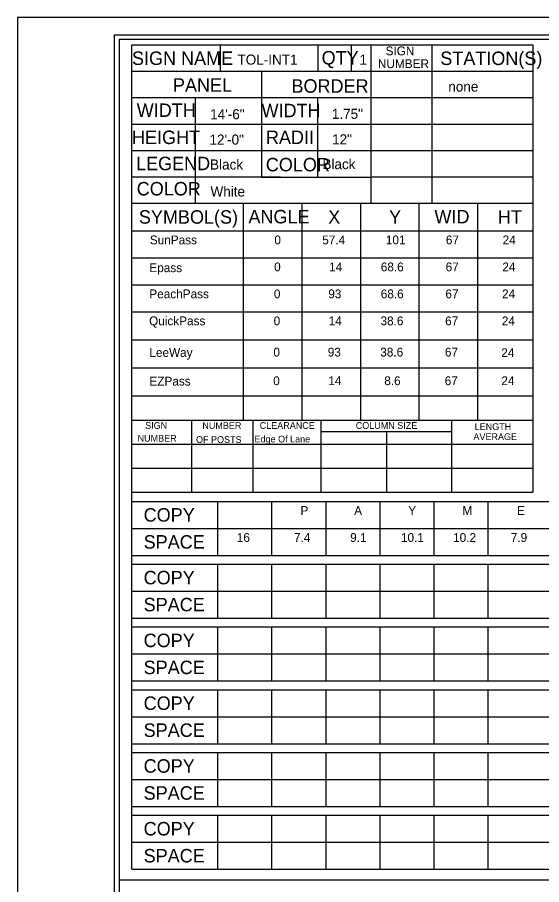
# Model space of a CAD drawing. Extents: x 17890628 to 17891459, y 17897314 to 17897992.
# Drawn here: x 17890701.35 to 17890724.69, y 17897458.18 to 17897496.82 of the extents above; entities that cross this region are included whole.
import ezdxf

# ---------------------------------------------------------------- set-up
doc = ezdxf.new("R2010")
doc.units = 0
for name, color, linetype in [('GSDims', 7, 'Continuous'), ('PlotBorder_dp', 7, 'Continuous'), ('SheetBorder_dp', 7, 'Continuous'), ('SheetLinesMisc2_dp', 7, 'Continuous'), ('TextMinor', 7, 'Continuous')]:
    doc.layers.add(name, color=color, linetype=linetype)

msp = doc.modelspace()

# ---------------------------------------------------------------- linework, layer by layer
at = {"layer": 'PlotBorder_dp'}
msp.add_lwpolyline([(17890701.346, 17897413.687), (17890830.745, 17897413.687), (17890830.745, 17897496.818), (17890701.346, 17897496.818)], close=True, dxfattribs=at)
at = {"layer": 'SheetBorder_dp'}
for q in [(17890705.659, 17897414.472), (17890826.432, 17897496.034)]:
    msp.add_line((17890705.659, 17897496.034), q, dxfattribs=at)
at = {"layer": 'SheetLinesMisc2_dp'}
for p, q in [((17890705.872, 17897495.849), (17890826.223, 17897495.849)), ((17890705.872, 17897495.849), (17890705.872, 17897420.931)), ((17890706.45, 17897458.862), (17890706.45, 17897495.599)), ((17890706.45, 17897495.599), (17890724.295, 17897495.599)), ((17890710.383, 17897495.599), (17890710.383, 17897494.422)), ((17890714.721, 17897495.599), (17890714.721, 17897494.422)), ((17890716.203, 17897495.599), (17890716.203, 17897494.422)), ((17890717.086, 17897495.599), (17890717.086, 17897488.533)), ((17890719.801, 17897495.599), (17890719.801, 17897488.533)), ((17890724.295, 17897495.599), (17890724.295, 17897475.661)), ((17890706.45, 17897494.422), (17890724.295, 17897494.422)), ((17890712.217, 17897494.422), (17890712.217, 17897489.698)), ((17890706.45, 17897493.244), (17890724.295, 17897493.244)), ((17890709.27, 17897493.244), (17890709.27, 17897488.533)), ((17890714.706, 17897493.231), (17890714.706, 17897489.698)), ((17890706.45, 17897492.066), (17890724.295, 17897492.066)), ((17890706.45, 17897490.888), (17890724.295, 17897490.888)), ((17890706.45, 17897489.711), (17890713.068, 17897489.711)), ((17890712.217, 17897489.698), (17890717.086, 17897489.698)), ((17890717.086, 17897489.711), (17890724.295, 17897489.711)), ((17890706.45, 17897488.533), (17890724.295, 17897488.533)), ((17890711.405, 17897488.51), (17890711.405, 17897478.866)), ((17890714.013, 17897488.51), (17890714.013, 17897478.866)), ((17890716.62, 17897488.51), (17890716.62, 17897478.866)), ((17890719.228, 17897488.51), (17890719.228, 17897478.866)), ((17890721.835, 17897488.51), (17890721.835, 17897478.866)), ((17890706.454, 17897487.307), (17890724.295, 17897487.307)), ((17890706.454, 17897486.105), (17890724.295, 17897486.105)), ((17890706.454, 17897484.902), (17890724.295, 17897484.902)), ((17890706.454, 17897483.7), (17890724.295, 17897483.7)), ((17890706.454, 17897482.45), (17890724.295, 17897482.45)), ((17890706.454, 17897481.2), (17890724.295, 17897481.2)), ((17890706.454, 17897479.95), (17890724.295, 17897479.95)), ((17890706.45, 17897478.866), (17890724.295, 17897478.866)), ((17890706.45, 17897478.866), (17890724.295, 17897478.866)), ((17890709.098, 17897478.866), (17890709.098, 17897475.661)), ((17890711.835, 17897478.866), (17890711.835, 17897475.661)), ((17890714.857, 17897478.866), (17890714.857, 17897475.661)), ((17890720.676, 17897478.866), (17890720.676, 17897475.661)), ((17890714.871, 17897478.362), (17890720.687, 17897478.362)), ((17890717.778, 17897478.362), (17890717.778, 17897475.661)), ((17890706.45, 17897477.798), (17890724.295, 17897477.798)), ((17890706.45, 17897476.729), (17890724.295, 17897476.729)), ((17890706.45, 17897475.661), (17890724.295, 17897475.661)), ((17890706.449, 17897475.25), (17890765.638, 17897475.25)), ((17890710.259, 17897475.25), (17890710.259, 17897472.846)), ((17890712.668, 17897475.25), (17890712.668, 17897472.846)), ((17890715.075, 17897475.25), (17890715.075, 17897472.846)), ((17890717.483, 17897475.25), (17890717.483, 17897472.846)), ((17890719.89, 17897475.25), (17890719.89, 17897472.846)), ((17890722.298, 17897475.25), (17890722.298, 17897472.846)), ((17890706.449, 17897474.048), (17890765.638, 17897474.048)), ((17890706.449, 17897472.846), (17890765.638, 17897472.846)), ((17890706.449, 17897472.453), (17890765.638, 17897472.453)), ((17890710.259, 17897472.453), (17890710.259, 17897470.049)), ((17890712.668, 17897472.453), (17890712.668, 17897470.049)), ((17890715.075, 17897472.453), (17890715.075, 17897470.049)), ((17890717.483, 17897472.453), (17890717.483, 17897470.049)), ((17890719.89, 17897472.453), (17890719.89, 17897470.049)), ((17890722.298, 17897472.453), (17890722.298, 17897470.049)), ((17890706.449, 17897471.251), (17890765.638, 17897471.251)), ((17890706.449, 17897470.049), (17890765.638, 17897470.049)), ((17890706.449, 17897469.657), (17890765.638, 17897469.657)), ((17890710.259, 17897469.657), (17890710.259, 17897467.252)), ((17890712.668, 17897469.657), (17890712.668, 17897467.252)), ((17890715.075, 17897469.657), (17890715.075, 17897467.252)), ((17890717.483, 17897469.657), (17890717.483, 17897467.252)), ((17890719.89, 17897469.657), (17890719.89, 17897467.252)), ((17890722.298, 17897469.657), (17890722.298, 17897467.252)), ((17890706.449, 17897468.454), (17890765.638, 17897468.454)), ((17890706.449, 17897467.252), (17890765.638, 17897467.252)), ((17890706.449, 17897466.86), (17890765.638, 17897466.86)), ((17890710.259, 17897466.86), (17890710.259, 17897464.455)), ((17890712.668, 17897466.86), (17890712.668, 17897464.455)), ((17890715.075, 17897466.86), (17890715.075, 17897464.455)), ((17890717.483, 17897466.86), (17890717.483, 17897464.455)), ((17890719.89, 17897466.86), (17890719.89, 17897464.455)), ((17890722.298, 17897466.86), (17890722.298, 17897464.455)), ((17890706.449, 17897465.658), (17890765.638, 17897465.658)), ((17890706.449, 17897464.455), (17890765.638, 17897464.455)), ((17890706.449, 17897464.063), (17890765.638, 17897464.063)), ((17890710.259, 17897464.063), (17890710.259, 17897461.659)), ((17890712.668, 17897464.063), (17890712.668, 17897461.659)), ((17890715.075, 17897464.063), (17890715.075, 17897461.659)), ((17890717.483, 17897464.063), (17890717.483, 17897461.659)), ((17890719.89, 17897464.063), (17890719.89, 17897461.659)), ((17890722.298, 17897464.063), (17890722.298, 17897461.659)), ((17890706.449, 17897462.861), (17890765.638, 17897462.861)), ((17890706.449, 17897461.659), (17890765.638, 17897461.659)), ((17890706.449, 17897461.267), (17890765.638, 17897461.267)), ((17890710.259, 17897461.267), (17890710.259, 17897458.862)), ((17890712.668, 17897461.267), (17890712.668, 17897458.862)), ((17890715.075, 17897461.267), (17890715.075, 17897458.862)), ((17890717.483, 17897461.267), (17890717.483, 17897458.862)), ((17890719.89, 17897461.267), (17890719.89, 17897458.862)), ((17890722.298, 17897461.267), (17890722.298, 17897458.862)), ((17890706.449, 17897460.065), (17890765.638, 17897460.065)), ((17890706.449, 17897458.862), (17890765.638, 17897458.862)), ((17890705.872, 17897458.39), (17890826.223, 17897458.39))]:
    msp.add_line(p, q, dxfattribs=at)

# ---------------------------------------------------------------- texts
at = {"layer": 'GSDims'}
for s, height, p in [('TOL-INT1', 0.4499, (17890711.147, 17897494.709)), ('1', 0.45, (17890716.577, 17897494.708)), ('none', 0.4499, (17890720.534, 17897493.508)), ('1.75"', 0.4499, (17890715.348, 17897492.294)), ('14\'-6"', 0.4499, (17890709.93, 17897492.277)), ('12\'-0"', 0.4499, (17890709.899, 17897491.147)), ('12"', 0.4499, (17890715.36, 17897491.159)), ('Black', 0.4499, (17890709.925, 17897490.037)), ('Black', 0.4499, (17890714.929, 17897490.055)), ('White', 0.4499, (17890709.945, 17897488.834)), ('SunPass', 0.3921, (17890707.245, 17897486.706)), ('0', 0.392, (17890712.79, 17897486.706)), ('57.4', 0.3921, (17890714.921, 17897486.706)), ('101', 0.3921, (17890717.753, 17897486.706)), ('67', 0.3921, (17890720.425, 17897486.706)), ('24', 0.3921, (17890722.95, 17897486.706)), ('Epass', 0.3921, (17890707.224, 17897485.466)), ('0', 0.392, (17890712.779, 17897485.503)), ('14', 0.3921, (17890715.228, 17897485.503)), ('68.6', 0.3921, (17890717.527, 17897485.503)), ('67', 0.3921, (17890720.415, 17897485.503)), ('24', 0.3921, (17890722.939, 17897485.503)), ('PeachPass', 0.3921, (17890707.223, 17897484.301)), ('0', 0.392, (17890712.768, 17897484.301)), ('93', 0.3921, (17890715.189, 17897484.301)), ('68.6', 0.3921, (17890717.526, 17897484.301)), ('67', 0.3921, (17890720.404, 17897484.301)), ('24', 0.3921, (17890722.928, 17897484.301)), ('QuickPass', 0.3921, (17890707.212, 17897483.099)), ('0', 0.392, (17890712.758, 17897483.099)), ('14', 0.3921, (17890715.206, 17897483.099)), ('38.6', 0.3921, (17890717.515, 17897483.099)), ('67', 0.3921, (17890720.393, 17897483.099)), ('24', 0.3921, (17890722.917, 17897483.099)), ('LeeWay', 0.3921, (17890707.225, 17897481.689)), ('0', 0.392, (17890712.747, 17897481.706)), ('93', 0.3921, (17890715.168, 17897481.706)), ('38.6', 0.3921, (17890717.504, 17897481.706)), ('67', 0.3921, (17890720.382, 17897481.706)), ('24', 0.3921, (17890722.891, 17897481.681)), ('EZPass', 0.3921, (17890707.226, 17897480.412)), ('0', 0.392, (17890712.738, 17897480.431)), ('14', 0.3921, (17890715.187, 17897480.431)), ('8.6', 0.3921, (17890717.682, 17897480.431)), ('67', 0.3921, (17890720.373, 17897480.431)), ('24', 0.3921, (17890722.897, 17897480.431)), ('P', 0.392, (17890713.953, 17897474.649)), ('A', 0.392, (17890716.342, 17897474.649)), ('Y', 0.392, (17890718.751, 17897474.649)), ('M', 0.392, (17890721.159, 17897474.649)), ('E', 0.392, (17890723.595, 17897474.649)), ('16', 0.3921, (17890711.115, 17897473.447)), ('7.4', 0.3921, (17890713.663, 17897473.447)), ('9.1', 0.3921, (17890716.165, 17897473.447)), ('10.1', 0.3921, (17890718.424, 17897473.447)), ('10.2', 0.3921, (17890720.748, 17897473.447)), ('7.9', 0.3921, (17890723.315, 17897473.447))]:
    msp.add_text(s, height=height, dxfattribs=at).set_placement(p)
at = {"layer": 'TextMinor'}
for s, height, p in [('SIGN', 0.3921, (17890717.741, 17897495.127)), ('SIGN NAME', 0.5999, (17890706.45, 17897494.697)), ('QTY', 0.5999, (17890714.892, 17897494.717)), ('STATION(S)', 0.5999, (17890720.176, 17897494.694)), ('NUMBER', 0.3921, (17890717.4, 17897494.556)), ('PANEL', 0.5999, (17890708.274, 17897493.501)), ('BORDER', 0.5999, (17890713.551, 17897493.46)), ('WIDTH', 0.5999, (17890706.661, 17897492.38)), ('WIDTH', 0.5999, (17890712.217, 17897492.368)), ('HEIGHT', 0.5999, (17890706.45, 17897491.173)), ('RADII', 0.5999, (17890712.414, 17897491.175)), ('LEGEND', 0.5999, (17890706.63, 17897490.008)), ('COLOR', 0.5999, (17890712.409, 17897489.957)), ('COLOR', 0.5999, (17890706.661, 17897488.884)), ('SYMBOL(S)', 0.5999, (17890706.757, 17897487.625)), ('ANGLE', 0.5999, (17890711.635, 17897487.638)), ('X', 0.6, (17890715.186, 17897487.625)), ('Y', 0.6, (17890717.897, 17897487.625)), ('WID', 0.5999, (17890719.916, 17897487.638)), ('HT', 0.5999, (17890722.743, 17897487.627)), ('SIGN', 0.3, (17890707.036, 17897478.485)), ('NUMBER', 0.3, (17890709.583, 17897478.481)), ('CLEARANCE', 0.3, (17890712.137, 17897478.483)), ('COLUMN SIZE', 0.29998, (17890716.412, 17897478.483)), ('LENGTH', 0.3, (17890721.708, 17897478.431)), ('NUMBER', 0.3, (17890706.7, 17897477.914)), ('OF POSTS', 0.3, (17890709.3, 17897477.857)), ('Edge Of Lane', 0.29998, (17890711.906, 17897477.879)), ('AVERAGE', 0.3, (17890721.652, 17897477.983)), ('COPY', 0.6, (17890706.969, 17897474.351)), ('SPACE', 0.6, (17890706.969, 17897473.148)), ('COPY', 0.6, (17890706.969, 17897471.557)), ('SPACE', 0.6, (17890706.969, 17897470.354)), ('COPY', 0.6, (17890706.969, 17897468.758)), ('SPACE', 0.6, (17890706.969, 17897467.555)), ('COPY', 0.6, (17890706.969, 17897465.961)), ('SPACE', 0.6, (17890706.969, 17897464.759)), ('COPY', 0.6, (17890706.969, 17897463.164)), ('SPACE', 0.6, (17890706.969, 17897461.961)), ('COPY', 0.6, (17890706.969, 17897460.368)), ('SPACE', 0.6, (17890706.969, 17897459.166))]:
    msp.add_text(s, height=height, dxfattribs=at).set_placement(p)

doc.saveas('drawing.dxf')
